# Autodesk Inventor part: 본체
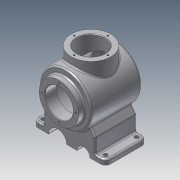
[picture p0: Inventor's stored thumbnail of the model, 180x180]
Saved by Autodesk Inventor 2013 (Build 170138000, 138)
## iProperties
Created: 2018-08
Part Number: 본체
Material: 알루미늄 6061
Document SubType Name: Modeling
Designer: Administrator
Density: 2.71 g/cm^3
Mass: 1886.06 g
Surface Area: 1087.48 cm^2
Volume: 695.962 cm^3
Author: Administrator
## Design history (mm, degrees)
sketch "스케치1"
  geometry: L1 (-60, 0)-(60, 0); L2 (-60, 0)-(-60, 38); L3 (-60, 38)-(-48, 38); L4 (-48, 38)-(-48, 50); L5 (-48, 50)-(48.671, 50); A1 r 116 centre (-56, 0) between (60, 0) and (48.671, 50); 2 further points
  constraints: 10 end point, 2 parallel, 2 perpendicular, 2 point on circle, 1 centre point, 1 coincident, 1 horizontal, 1 midpoint, 1 point on line
  dimensions: "d0" = 120 distance of L1.start L1.end; "d1" = 116 radius of A1; "d2" = 100 diameter of L5 L1; "d3" = 76 diameter of L3 L1; "d4" = 12 distance of L2.end L3.end
revolve "회전1" sketch "스케치1" stored, may be unused: angle "d5" = 90 deg
sketch "스케치2"
  geometry: L1 (-60, -38)-(-60, 38) reference; L2 (-60, 38)-(-48, 38) reference; L3 (-48, 38)-(-48, 50) reference; L4 (-48, 50)-(48.671, 50) reference; L5 (48.671, -50)-(-48, -50) reference; L6 (-48, -50)-(-48, -38) reference; L7 (-48, -38)-(-60, -38) reference; L8 (-60, 27)-(-38, 27); L9 (-38, 27)-(-38, 40); L10 (-38, 40)-(42.163, 40); L11 (-60, 0)-(50, 0); L12 (-60, -38)-(-60, 38) reference; L13 (-60, 38)-(-48, 38) reference; L14 (-48, 38)-(-48, 50) reference; L15 (-48, 50)-(48.671, 50) reference; L16 (48.671, -50)-(-48, -50) reference; L17 (-48, -50)-(-48, -38) reference; L18 (-48, -38)-(-60, -38) reference; L19 (-60, 27)-(-60, 0); A1 r 116 centre (-56, 0) between (48.671, -50) and (48.671, 50) reference; A2 r 116 centre (-56, 0) between (48.671, -50) and (48.671, 50) reference; A3 r 116 centre (-56, 0) between (48.671, -50) and (48.671, 50) reference; A4 r 106 centre (-56, 0) between (50, 0) and (42.163, 40); 1 further point
  constraints: 10 end point, 2 parallel, 2 perpendicular, 2 point on circle, 2 point on line, 1 centre point, 1 midpoint
  dimensions: "d8" = 110 distance of L11.start L11.end; "d9" = 80 diameter of L10 L11; "d10" = 54 diameter of L8 L11; "d11" = 22 distance of L8.start L8.end; "d12" = 106 radius of A4
revolve "회전2" sketch "스케치2" stored, may be unused: angle "d13" = 90 deg
sketch "스케치3"
  geometry: L1 (0, 0)-(0, 32.5); C1 r 38 at (0, 0) reference; 1 further point
  constraints: 2 end point, 1 coincident, 1 vertical
  dimensions: "d15" = 32.5 distance of L1.start L1.end
hole "구멍1" sketch "스케치3" at (0, 32.5) diameter "d16" = 3.242; stored, may be unused: countersink angle "d20" = 90 deg, drill point angle "d22" = 118 deg; dims "d17" = 8, "d18" = 4, "d19" = 2, "d21" = 10
node "작업 평면1"
sketch "스케치4"
  geometry: L1 (48, 50)-(48, -50) reference; L2 (48, 50)-(-48.671, 50) reference; C1 r 38 at (-2, 0); 1 further point
  constraints: 1 centre point, 1 coincident
  dimensions: "d27" = 76 diameter of C1; "d83" = 50 distance from line of L1 point (-2, 0); "d84" = 50 distance from line of point (-2, 0) L2
extrude "돌출1" join sketch "스케치4" stored distance "d28" = 10; taper "d29" = 0 deg
sketch "스케치5"
  geometry: C1 r 38 at (0, 0) reference; C2 r 27 at (0, 0)
  constraints: 1 centre point, 1 coincident
  dimensions: "d30" = 54 diameter of C2
extrude "돌출2" cut sketch "스케치5" stored distance "d31" = 10; taper "d32" = 0 deg
sketch "스케치6"
  geometry: L1 (0, 0)-(0, 32.5); C1 r 38 at (0, 0) reference; 1 further point
  constraints: 2 end point, 1 coincident, 1 vertical
  dimensions: "d33" = 32.5 distance of L1.start L1.end
hole "구멍2" sketch "스케치6" at (0, 32.5) diameter "d34" = 3.242; stored, may be unused: countersink angle "d38" = 90 deg, drill point angle "d40" = 118 deg; dims "d35" = 8, "d36" = 4, "d37" = 2, "d39" = 10
node "작업 평면2"
sketch "스케치8"
  geometry: L1 (60, 38)-(60, -38) reference; L2 (48, 50)-(48, -50) reference; L3 (40, -70)-(-40, -70); L4 (-40, -70)-(-40, 70); L5 (-40, 70)-(40, 70); L6 (40, 70)-(40, -70); L7 (40, -70)-(-40, 70); L8 (-40, -70)-(40, 70); 3 further points
  constraints: 12 end point, 3 midpoint, 2 parallel, 1 coincident, 1 horizontal, 1 perpendicular
  dimensions: "d45" = 80 distance of L4.end L5.end; "d46" = 140 distance of L3.end L4.end; "d48" = 8 distance between parallel lines of L6 L2
extrude "돌출3" join sketch "스케치8" distance "d49" = 10; taper "d50" = 0 deg
fillet "모깎기1" dims "d51" = 10
sketch "스케치9"
  geometry: A1 r 10 centre (-30, -60) between (-40, -60) and (-30, -70) reference; A2 r 10 centre (30, -60) between (30, -70) and (40, -60) reference; A3 r 10 centre (30, 60) between (40, 60) and (30, 70) reference; A4 r 10 centre (-30, 60) between (-30, 70) and (-40, 60) reference; 5 further points
  constraints: 4 coincident
hole "구멍3" sketch "스케치9" at (30, -60), (-30, -60), (-30, 60), (30, 60) diameter "d52" = 8; stored, may be unused: countersink angle "d56" = 90 deg, drill point angle "d58" = 118 deg; dims "d53" = 8, "d54" = 4, "d55" = 2, "d57" = 10
sketch "스케치10"
  geometry: L1 (0, 10)-(120, 10) reference; L2 (0, 0)-(0, 10) reference; L3 (19.696, 52.41)-(-10, 10); L4 (10, 38.563)-(10, 10); L5 (-10, 10)-(-10, 0) reference; L6 (130, 0)-(130, 10) reference; L7 (100.304, 52.41)-(130, 10); L8 (110, 38.563)-(110, 10); A1 r 50 centre (60, 82) between (19.696, 52.41) and (100.304, 52.41) reference; A2 r 50 centre (60, 82) between (19.696, 52.41) and (100.304, 52.41) reference; 1 further point
  constraints: 8 end point, 5 point on line, 4 point on circle, 2 perpendicular
  dimensions: "d60" = 35 deg angle of L2 L3; "d61" = 20 distance from line of L5 L4.end; "d62" = 35 deg angle of L7 L6; "d63" = 20 distance between parallel lines of L6 L8
extrude "돌출4" join sketch "스케치10" distance "d64" = 80; taper "d65" = 0 deg
sketch "스케치11"
  geometry: L1 (120, 0)-(0, 0) reference; C1 r 12.5 at (32.5, 0); C2 r 17.5 at (82.5, 0); A1 r 50 centre (60, 82) between (19.696, 52.41) and (100.304, 52.41) reference
  constraints: 2 centre point, 2 point on line
  dimensions: "d66" = 25 diameter of C1; "d67" = 35 diameter of C2; "d68" = 22.5 horizontal distance of C2.centre A1.centre; "d69" = 27.5 horizontal distance of A1.centre C1.centre
extrude "돌출5" cut sketch "스케치11" stored distance "d70" = 80; taper "d71" = 0 deg
chamfer "모따기1" distance "d72" = 1; stored, may be unused: second distance "d73" = 2, angle "d74" = 45 deg
fillet "모깎기2" dims "d75" = 3
fillet "모깎기3" dims "d76" = 3
fillet "모깎기4" dims "d77" = 3
fillet "모깎기5" dims "d78" = 3
node "작업 평면3"
sketch "스케치12"
  geometry: C1 r 32.5 at (0, 0); 1 further point
  constraints: 1 centre point, 1 coincident, 1 other
  dimensions: "d80" = 65 diameter of C1
feature "엠보싱1" sketch "스케치12" dims "d0" = 120, "d1" = 116, "d2" = 100, "d3" = 76, "d4" = 12, "d81" = 0.5, "d82" = 0
node "솔리드1"
pattern_circular "원형 패턴1" dims angle "d24" = 360 deg
pattern_circular "원형 패턴2" dims angle "d42" = 360 deg
node "투영된 루프1"
node "절단 모서리 투영1"
node "절단 모서리 투영2"
other parameters: "d26" = 65, "d44" = -82, "d79" = 63
